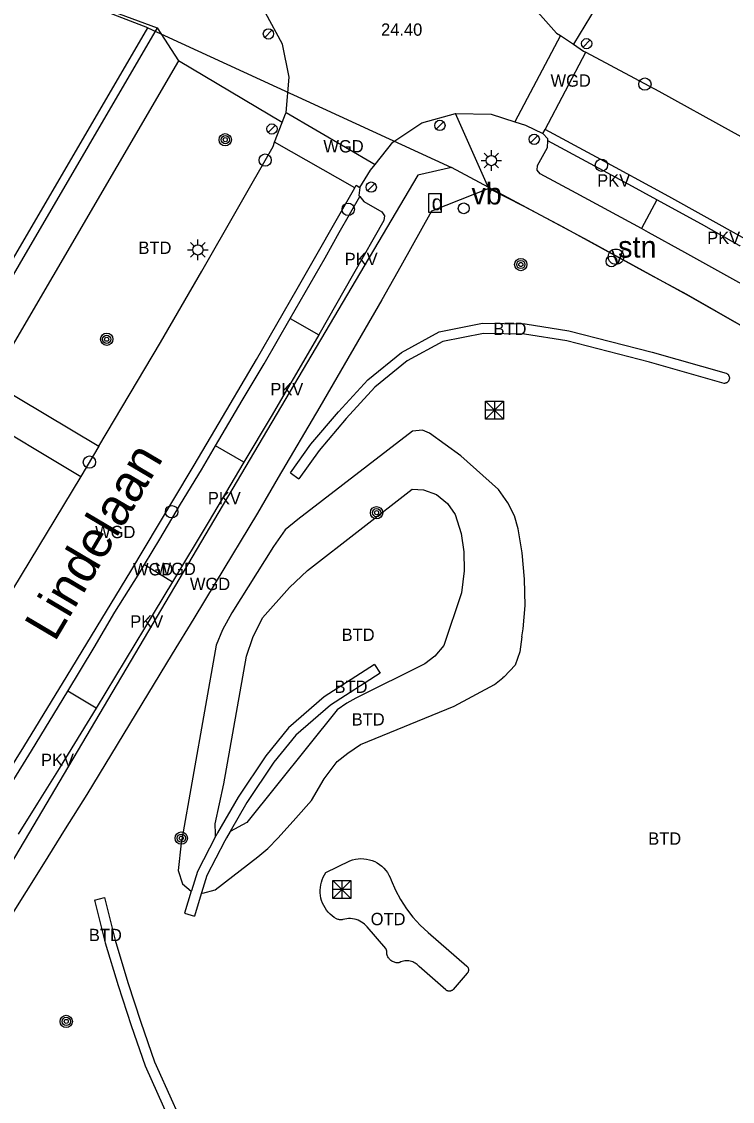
# Model space of a CAD drawing. Extents: x 198240 to 198429, y 356553 to 356721.
# Drawn here: x 198292.1 to 198326.7, y 356629.6 to 356682.2 of the extents above; entities that cross this region are included whole.
import ezdxf

# ---------------------------------------------------------------- set-up
doc = ezdxf.new("R2010")
doc.units = 0
for name, color, linetype in [('Afsluitpaal', 7, 'Continuous'), ('Afvalbak', 7, 'Continuous'), ('begroeid terreindeel kenmerkpunt', 7, 'Continuous'), ('BOOM', 7, 'Continuous'), ('Dispenser', 7, 'Continuous'), ('Grens beheer openbare ruimte wegbeheer', 7, 'Continuous'), ('grens individueel parkeervak', 7, 'Continuous'), ('Grens maaiveld', 7, 'Continuous'), ('Hoogtepunt', 7, 'Continuous'), ('identificerend kenmerkpunt parkeervak', 7, 'Continuous'), ('kant verharding', 7, 'Continuous'), ('kolk', 7, 'Continuous'), ('LICHTMAST', 7, 'Continuous'), ('onbegroeid terreindeel kenmerkpunt', 7, 'Continuous'), ('openbare ruimte label tekst', 7, 'Continuous'), ('perceelsgrens_definitief', 7, 'Continuous'), ('Speelvoorziening', 7, 'Continuous'), ('straatnaambord', 7, 'Continuous'), ('Verkeersbordpaal', 7, 'Continuous'), ('vlakafsluiter', 7, 'Continuous'), ('wegdeel kenmerkpunt', 7, 'Continuous'), ('weginrichtingselement lijn', 7, 'Continuous')]:
    doc.layers.add(name, color=color, linetype=linetype)

msp = doc.modelspace()

# ---------------------------------------------------------------- linework, layer by layer
at = {"layer": 'Afsluitpaal'}
for p, q in [((198304.255, 356681.768), (198303.905, 356681.411)), ((198319.751, 356681.296), (198319.401, 356680.939)), ((198304.428, 356677.142), (198304.078, 356676.785)), ((198312.607, 356677.317), (198312.257, 356676.96)), ((198317.2, 356676.638), (198316.85, 356676.281)), ((198309.263, 356674.313), (198308.913, 356673.956))]:
    msp.add_line(p, q, dxfattribs=at)
for centre in [(198304.082, 356681.588), (198319.578, 356681.116), (198304.255, 356676.962), (198312.434, 356677.137), (198317.027, 356676.458), (198309.09, 356674.133)]:
    msp.add_circle(centre, 0.25, dxfattribs=at)
at = {"layer": 'Afvalbak'}
msp.add_circle((198321.005, 356670.743), 0.375, dxfattribs=at)
msp.add_circle((198321.005, 356670.743), 0.375, dxfattribs=at)
at = {"layer": 'BOOM'}
for centre, radius in [((198301.981, 356676.439), 0.3), ((198301.981, 356676.439), 0.2), ((198301.981, 356676.439), 0.1), ((198316.373, 356670.362), 0.3), ((198316.373, 356670.362), 0.2), ((198316.373, 356670.362), 0.1), ((198296.207, 356666.724), 0.3), ((198296.207, 356666.724), 0.2), ((198296.207, 356666.724), 0.1), ((198309.35, 356658.281), 0.3), ((198309.35, 356658.281), 0.2), ((198309.35, 356658.281), 0.1), ((198299.841, 356642.437), 0.3), ((198299.841, 356642.437), 0.2), ((198299.841, 356642.437), 0.1), ((198294.238, 356633.513), 0.3), ((198294.238, 356633.513), 0.2), ((198294.238, 356633.513), 0.1)]:
    msp.add_circle(centre, radius, dxfattribs=at)
at = {"layer": 'Dispenser'}
msp.add_lwpolyline([(198311.878, 356672.913), (198312.512, 356672.913), (198312.512, 356673.801), (198311.878, 356673.801)], close=True, dxfattribs=at)
at = {"layer": 'Grens beheer openbare ruimte wegbeheer'}
for p, q in [((198318.297, 356681.511), (198316.075, 356677.313)), ((198304.947, 356677.77), (198309.283, 356675.24))]:
    msp.add_line(p, q, dxfattribs=at)
at = {"layer": 'grens individueel parkeervak'}
for p, q in [((198323.004, 356673.505), (198322.242, 356672.111)), ((198305.144, 356667.741), (198306.53, 356666.941)), ((198302.887, 356660.742), (198301.505, 356661.539)), ((198298.049, 356655.752), (198299.406, 356654.919)), ((198295.687, 356648.769), (198294.317, 356649.594))]:
    msp.add_line(p, q, dxfattribs=at)
at = {"layer": 'Grens maaiveld'}
for p, q in [((198317.553, 356676.932), (198319.532, 356680.702)), ((198317.45, 356676.736), (198317.553, 356676.932)), ((198308.283, 356674.098), (198304.386, 356676.319)), ((198310.555, 356666.086), (198312.403, 356667.091)), ((198312.403, 356667.091), (198314.505, 356667.501)), ((198314.505, 356667.501), (198316.591, 356667.47)), ((198316.591, 356667.47), (198318.709, 356667.13)), ((198318.709, 356667.13), (198322.776, 356666.095)), ((198312.575, 356666.615), (198310.835, 356665.67)), ((198314.549, 356667.001), (198312.575, 356666.615)), ((198316.547, 356666.97), (198314.549, 356667.001)), ((198318.607, 356666.64), (198316.547, 356666.97)), ((198322.646, 356665.613), (198318.607, 356666.64)), ((198308.919, 356664.751), (198310.555, 356666.086)), ((198322.776, 356666.095), (198326.379, 356665.067)), ((198310.835, 356665.67), (198309.263, 356664.387)), ((198326.273, 356664.577), (198322.646, 356665.613)), ((198326.379, 356665.067), (198326.398, 356665.057)), ((198326.398, 356665.057), (198326.417, 356665.045)), ((198326.417, 356665.045), (198326.434, 356665.032)), ((198326.434, 356665.032), (198326.45, 356665.018)), ((198326.45, 356665.018), (198326.465, 356665.002)), ((198326.465, 356665.002), (198326.479, 356664.985)), ((198326.479, 356664.985), (198326.491, 356664.967)), ((198326.491, 356664.967), (198326.501, 356664.948)), ((198326.501, 356664.948), (198326.51, 356664.928)), ((198307.5, 356663.191), (198308.919, 356664.751)), ((198326.294, 356664.578), (198326.273, 356664.577)), ((198326.316, 356664.581), (198326.294, 356664.578)), ((198326.337, 356664.585), (198326.316, 356664.581)), ((198326.358, 356664.592), (198326.337, 356664.585)), ((198326.378, 356664.6), (198326.358, 356664.592)), ((198326.397, 356664.61), (198326.378, 356664.6)), ((198326.416, 356664.621), (198326.397, 356664.61)), ((198326.433, 356664.634), (198326.416, 356664.621)), ((198326.45, 356664.648), (198326.433, 356664.634)), ((198326.465, 356664.664), (198326.45, 356664.648)), ((198326.478, 356664.681), (198326.465, 356664.664)), ((198326.49, 356664.699), (198326.478, 356664.681)), ((198326.501, 356664.718), (198326.49, 356664.699)), ((198326.51, 356664.737), (198326.501, 356664.718)), ((198326.51, 356664.928), (198326.518, 356664.908)), ((198326.517, 356664.758), (198326.51, 356664.737)), ((198326.523, 356664.779), (198326.517, 356664.758)), ((198326.518, 356664.908), (198326.523, 356664.887)), ((198326.523, 356664.887), (198326.527, 356664.865)), ((198326.526, 356664.8), (198326.523, 356664.779)), ((198326.528, 356664.822), (198326.526, 356664.8)), ((198326.527, 356664.865), (198326.528, 356664.844)), ((198326.528, 356664.844), (198326.528, 356664.822)), ((198309.263, 356664.387), (198307.874, 356662.861)), ((198306.153, 356661.617), (198307.5, 356663.191)), ((198307.874, 356662.861), (198306.547, 356661.309)), ((198305.155, 356660.219), (198306.153, 356661.617)), ((198306.547, 356661.309), (198305.561, 356659.929)), ((198305.155, 356660.219), (198305.561, 356659.929)), ((198309.252, 356650.89), (198309.522, 356650.47)), ((198300.326, 356639.856), (198299.998, 356638.792)), ((198300.808, 356639.723), (198300.476, 356638.644)), ((198299.998, 356638.792), (198300.476, 356638.644))]:
    msp.add_line(p, q, dxfattribs=at)
for points in [[(198372.981, 356641.75), (198367.706, 356645.661), (198366.187, 356646.802), (198364.538, 356647.958), (198362.833, 356649.176), (198361.195, 356650.33), (198359.548, 356651.463), (198357.799, 356652.691), (198352.878, 356655.977), (198347.848, 356659.26), (198346.187, 356660.353), (198344.459, 356661.463), (198342.759, 356662.483), (198340.988, 356663.592), (198339.269, 356664.603), (198335.834, 356666.664), (198332.346, 356668.725), (198327.175, 356671.678), (198323.573, 356673.677), (198320.05, 356675.592), (198317.553, 356676.932)], [(198286.537, 356637.898), (198290.083, 356643.54), (198292.172, 356646.883), (198294.288, 356650.332), (198295.232, 356651.912), (198297.381, 356655.439), (198299.42, 356658.858), (198300.465, 356660.59), (198301.471, 356662.302), (198303.507, 356665.731), (198304.495, 356667.459), (198305.49, 356669.172), (198308.283, 356674.098)], [(198308.283, 356674.098), (198308.355, 356674.225), (198308.541, 356674.108)], [(198309.252, 356650.89), (198306.8, 356649.312), (198305.062, 356647.807), (198303.951, 356646.439), (198302.602, 356644.434), (198301.602, 356642.698), (198301.516, 356642.533)], [(198309.522, 356650.47), (198307.1, 356648.91), (198305.422, 356647.457), (198304.353, 356646.141), (198303.026, 356644.17), (198302.217, 356642.764)], [(198301.509, 356642.519), (198300.621, 356640.812), (198300.33, 356639.871)], [(198301.96, 356642.303), (198301.085, 356640.622), (198300.821, 356639.766)], [(198308.316, 356641.414), (198308.452, 356641.434), (198308.59, 356641.441), (198308.728, 356641.436), (198308.865, 356641.418), (198309, 356641.388), (198309.132, 356641.346), (198309.259, 356641.293), (198309.381, 356641.228), (198309.497, 356641.153), (198309.606, 356641.067), (198309.706, 356640.972), (198309.797, 356640.869), (198309.879, 356640.758), (198309.951, 356640.639), (198310.012, 356640.515), (198310.061, 356640.386), (198310.267, 356639.904), (198310.513, 356639.442), (198310.798, 356639.001), (198311.119, 356638.587), (198311.474, 356638.201), (198311.86, 356637.846), (198313.744, 356636.204), (198313.759, 356636.19), (198313.772, 356636.174), (198313.785, 356636.157), (198313.796, 356636.14), (198313.805, 356636.121), (198313.813, 356636.101), (198313.819, 356636.081), (198313.823, 356636.061), (198313.825, 356636.04), (198313.825, 356636.019), (198313.824, 356635.999), (198313.821, 356635.978), (198313.816, 356635.958), (198313.81, 356635.938), (198313.801, 356635.919), (198313.791, 356635.901), (198313.78, 356635.883), (198313.767, 356635.867), (198313.071, 356635.069), (198313.056, 356635.053), (198313.04, 356635.039), (198313.023, 356635.027), (198313.005, 356635.016), (198312.986, 356635.006), (198312.966, 356634.998), (198312.945, 356634.992), (198312.924, 356634.988), (198312.903, 356634.986), (198312.882, 356634.985), (198312.861, 356634.986), (198312.84, 356634.99), (198312.819, 356634.995), (198312.799, 356635.001), (198312.779, 356635.01), (198312.76, 356635.02), (198312.742, 356635.032), (198312.726, 356635.045), (198311.422, 356636.182), (198311.379, 356636.231), (198311.333, 356636.277), (198311.282, 356636.318), (198311.228, 356636.355), (198311.171, 356636.387), (198311.111, 356636.414), (198311.05, 356636.436), (198310.987, 356636.453), (198310.922, 356636.465), (198310.857, 356636.47), (198310.792, 356636.471), (198310.726, 356636.465), (198310.662, 356636.454), (198310.599, 356636.438), (198310.537, 356636.416), (198310.477, 356636.39), (198310.457, 356636.381), (198310.437, 356636.374), (198310.415, 356636.368), (198310.394, 356636.365), (198310.372, 356636.364), (198310.35, 356636.364), (198310.304, 356636.369), (198310.259, 356636.378), (198310.214, 356636.391), (198310.171, 356636.408), (198310.129, 356636.428), (198310.089, 356636.452), (198310.051, 356636.479), (198310.016, 356636.509), (198309.983, 356636.542), (198309.954, 356636.578), (198309.927, 356636.616), (198309.904, 356636.656), (198309.884, 356636.698), (198309.868, 356636.742), (198309.856, 356636.787), (198309.847, 356636.832), (198309.842, 356636.879), (198309.842, 356636.925), (198309.841, 356636.944), (198309.839, 356636.963), (198309.835, 356636.982), (198309.83, 356637.001), (198309.823, 356637.018), (198309.814, 356637.035), (198309.803, 356637.052), (198309.792, 356637.067), (198308.897, 356638.111), (198308.833, 356638.18), (198308.765, 356638.244), (198308.691, 356638.302), (198308.613, 356638.354), (198308.531, 356638.399), (198308.445, 356638.438), (198308.357, 356638.469), (198308.266, 356638.493), (198308.174, 356638.509), (198308.08, 356638.518), (198307.986, 356638.519), (198307.893, 356638.512), (198307.8, 356638.498), (198307.709, 356638.476), (198307.67, 356638.467), (198307.63, 356638.462), (198307.59, 356638.461), (198307.55, 356638.463), (198307.51, 356638.47), (198307.471, 356638.48), (198307.434, 356638.494), (198307.398, 356638.512), (198307.287, 356638.58), (198307.182, 356638.657), (198307.084, 356638.742), (198306.994, 356638.835), (198306.912, 356638.936), (198306.838, 356639.043), (198306.774, 356639.155), (198306.719, 356639.273), (198306.675, 356639.395), (198306.641, 356639.52), (198306.617, 356639.648), (198306.604, 356639.777), (198306.603, 356639.907), (198306.612, 356640.036), (198306.632, 356640.165), (198306.662, 356640.291), (198306.703, 356640.414), (198306.754, 356640.533), (198306.815, 356640.648), (198306.886, 356640.757), (198308.05, 356641.339), (198308.181, 356641.382), (198308.316, 356641.414)]]:
    msp.add_lwpolyline(points, dxfattribs=at)
at = {"layer": 'kant verharding'}
for p, q in [((198324.168, 356689.714), (198318.94, 356681.083)), ((198318.297, 356681.511), (198318.94, 356681.083)), ((198304.756, 356677.274), (198299.71, 356680.28)), ((198304.756, 356677.274), (198304.922, 356677.704)), ((198304.922, 356677.704), (198304.947, 356677.77)), ((198304.386, 356676.319), (198304.756, 356677.274)), ((198295.83, 356661.522), (198294.945, 356660.041)), ((198301.516, 356642.533), (198301.509, 356642.519)), ((198300.33, 356639.871), (198300.326, 356639.856)), ((198300.821, 356639.766), (198300.808, 356639.723)), ((198295.609, 356639.419), (198296.093, 356639.541))]:
    msp.add_line(p, q, dxfattribs=at)
for points in [[(198239.787, 356698.674), (198277.877, 356688.756), (198279.573, 356688.328), (198281.722, 356687.74), (198283.655, 356687.172), (198285.635, 356686.576), (198287.401, 356686.002), (198289.29, 356685.363), (198291.23, 356684.694), (198293.016, 356684.031), (198294.971, 356683.265), (198298.672, 356681.879)], [(198317.228, 356690.174), (198316.569, 356688.783), (198316.101, 356687.293), (198316.037, 356685.727), (198316.368, 356684.197), (198317.077, 356682.795), (198318.116, 356681.632), (198318.297, 356681.511)], [(198304.947, 356677.77), (198305.092, 356679.489), (198304.764, 356681.085), (198303.938, 356682.621), (198302.718, 356683.87), (198301.331, 356684.631), (198300.854, 356684.816)], [(198298.672, 356681.879), (198281.729, 356652.893), (198280.805, 356651.439), (198272.725, 356638.444), (198270.553, 356635.006), (198264.327, 356625.306), (198262.967, 356623.203)], [(198318.94, 356681.083), (198319.431, 356680.756), (198319.532, 356680.702)], [(198299.71, 356680.28), (198290.566, 356664.656), (198295.83, 356661.522)], [(198319.532, 356680.702), (198323.087, 356678.797), (198326.611, 356676.862), (198328.348, 356675.892), (198331.824, 356673.931), (198333.616, 356672.898)], [(198309.283, 356675.24), (198310.144, 356676.323), (198311.551, 356677.266), (198313.199, 356677.719)], [(198313.199, 356677.719), (198314.929, 356677.677), (198316.075, 356677.313)], [(198316.075, 356677.313), (198316.599, 356677.146), (198317.45, 356676.736)], [(198317.684, 356676.383), (198317.69, 356676.483), (198317.45, 356676.736)], [(198295.83, 356661.522), (198298.827, 356666.573), (198300.844, 356670.034), (198304.306, 356676.111), (198304.386, 356676.319)], [(198322.242, 356672.111), (198319.074, 356673.829), (198317.31, 356674.771), (198317.161, 356674.963), (198317.181, 356675.183), (198317.664, 356676.064), (198317.684, 356676.383)], [(198323.004, 356673.505), (198321.63, 356674.257), (198317.684, 356676.383)], [(198308.541, 356674.108), (198309.058, 356674.957), (198309.283, 356675.24)], [(198314.814, 356674.063), (198312.029, 356672.963), (198310.527, 356670.277), (198309.599, 356668.644), (198306.585, 356663.435), (198304.556, 356659.989), (198303.55, 356658.264), (198301.482, 356654.843), (198300.453, 356653.124), (198299.402, 356651.409), (198295.243, 356644.568), (198294.178, 356642.884), (198293.122, 356641.182), (198288.971, 356634.577)], [(198308.541, 356674.108), (198308.488, 356673.718), (198308.529, 356673.667)], [(198352.51, 356651.714), (198350.276, 356653.164), (198348.4, 356654.399), (198343.742, 356657.419), (198341.543, 356658.825), (198339.43, 356660.09), (198337.442, 356661.338), (198333.99, 356663.38), (198332.34, 356664.377), (198330.533, 356665.43), (198328.787, 356666.422), (198324.464, 356668.899), (198322.677, 356669.861), (198318.431, 356672.186), (198316.529, 356673.188), (198314.814, 356674.063)], [(198305.144, 356667.741), (198306.85, 356670.689), (198307.533, 356671.918), (198308.529, 356673.667)], [(198308.529, 356673.667), (198308.721, 356673.427), (198309.597, 356672.934), (198309.739, 356672.74), (198309.699, 356672.508), (198308.226, 356669.905), (198306.53, 356666.941)], [(198328.199, 356670.612), (198325.17, 356672.32), (198323.004, 356673.505)], [(198327.419, 356669.24), (198324.358, 356670.953), (198322.598, 356671.918), (198322.242, 356672.111)], [(198301.505, 356661.539), (198302.802, 356663.746), (198303.88, 356665.536), (198305.144, 356667.741)], [(198306.53, 356666.941), (198306.24, 356666.433), (198304.217, 356662.969), (198302.887, 356660.742)], [(198284.31, 356653.964), (198289.691, 356663.193), (198294.945, 356660.041)], [(198316.429, 356652.235), (198316.484, 356652.634), (198316.587, 356653.755), (198316.545, 356655.042), (198316.432, 356656.331), (198316.25, 356657.493), (198316.059, 356658.12), (198315.746, 356658.761), (198315.289, 356659.414), (198313.447, 356661.057), (198311.934, 356662.151), (198311.591, 356662.306), (198311.105, 356662.242), (198305.509, 356657.956), (198304.902, 356657.439), (198304.328, 356656.64), (198302.293, 356653.401), (198301.842, 356652.58), (198301.543, 356651.839), (198299.839, 356642.193), (198299.689, 356640.868), (198299.905, 356640.205), (198300.326, 356639.856)], [(198298.049, 356655.752), (198298.798, 356656.987), (198299.804, 356658.69), (198300.826, 356660.375), (198301.505, 356661.539)], [(198302.887, 356660.742), (198301.151, 356657.811), (198299.406, 356654.919)], [(198294.945, 356660.041), (198291.623, 356654.549), (198290.581, 356652.845), (198289.527, 356651.142)], [(198301.509, 356642.519), (198301.499, 356642.653), (198301.486, 356643.136), (198301.904, 356645.088), (198303.008, 356651.291), (198303.328, 356652.204), (198303.798, 356653.155), (198305.104, 356654.635), (198305.98, 356655.468), (198311.087, 356659.428), (198311.634, 356659.392), (198312.267, 356659.162), (198312.803, 356658.731), (198313.175, 356658.191), (198313.468, 356657.265), (198313.6, 356656.369), (198313.61, 356655.443), (198313.478, 356654.379), (198312.628, 356651.822), (198312.184, 356651.3), (198311.698, 356650.93), (198308.346, 356649.254), (198307.895, 356649.01), (198307.426, 356648.683), (198303.03, 356643.205), (198302.217, 356642.764)], [(198294.317, 356649.594), (198295.594, 356651.712), (198296.608, 356653.444), (198297.739, 356655.236), (198298.049, 356655.752)], [(198299.406, 356654.919), (198298.054, 356652.665), (198295.687, 356648.769)], [(198316.429, 356652.235), (198316.327, 356651.5), (198316.096, 356650.851), (198315.561, 356650.286), (198315.5, 356650.239)], [(198300.821, 356639.766), (198300.889, 356639.758), (198301.484, 356639.927), (198303.572, 356641.529), (198304.059, 356641.936), (198304.551, 356642.45), (198305.422, 356643.411), (198306.175, 356644.274), (198306.8, 356645.32), (198307.426, 356646.163), (198307.946, 356646.569), (198308.572, 356646.993), (198313.128, 356648.861), (198315.084, 356649.919), (198315.5, 356650.239)], [(198290.544, 356643.476), (198292.54, 356646.68), (198294.317, 356649.594)], [(198295.687, 356648.769), (198293.888, 356645.827), (198292.831, 356644.137), (198291.898, 356642.624)], [(198302.217, 356642.764), (198302.04, 356642.458), (198301.96, 356642.303)], [(198295.609, 356639.419), (198296.132, 356637.335), (198296.768, 356635.258), (198297.401, 356633.318), (198298.077, 356631.357), (198298.966, 356629.358), (198299.856, 356627.399), (198300.835, 356625.473), (198301.904, 356623.589), (198303.061, 356621.754), (198304.4, 356620.082), (198306.161, 356618.711), (198308.223, 356617.871), (198310.375, 356617.558), (198311.788, 356617.522), (198313.219, 356617.658)], [(198296.093, 356639.541), (198296.614, 356637.469), (198297.244, 356635.408), (198297.875, 356633.478), (198298.543, 356631.541), (198299.422, 356629.562), (198300.306, 356627.615), (198301.275, 356625.709), (198302.334, 356623.845), (198303.469, 356622.044), (198304.754, 356620.44), (198306.413, 356619.147), (198308.355, 356618.357), (198310.417, 356618.058), (198311.77, 356618.022), (198313.171, 356618.156)]]:
    msp.add_lwpolyline(points, dxfattribs=at)
at = {"layer": 'kolk'}
for centre in [(198322.416, 356679.144), (198303.924, 356675.446), (198320.299, 356675.195), (198307.966, 356673.05), (198295.365, 356660.745), (198299.371, 356658.33)]:
    msp.add_circle(centre, 0.3, dxfattribs=at)
at = {"layer": 'LICHTMAST'}
for p, q in [((198314.76, 356675.601), (198314.583, 356675.778)), ((198314.937, 356675.674), (198314.937, 356675.924)), ((198315.114, 356675.601), (198315.291, 356675.778)), ((198314.437, 356675.424), (198314.687, 356675.424)), ((198314.583, 356675.07), (198314.76, 356675.247)), ((198314.937, 356674.924), (198314.937, 356675.174)), ((198315.291, 356675.07), (198315.114, 356675.247)), ((198315.187, 356675.424), (198315.437, 356675.424)), ((198300.473, 356671.251), (198300.296, 356671.428)), ((198300.65, 356671.324), (198300.65, 356671.574)), ((198300.827, 356671.251), (198301.004, 356671.428)), ((198300.15, 356671.074), (198300.4, 356671.074)), ((198300.296, 356670.72), (198300.473, 356670.897)), ((198300.65, 356670.574), (198300.65, 356670.824)), ((198301.004, 356670.72), (198300.827, 356670.897)), ((198300.9, 356671.074), (198301.15, 356671.074))]:
    msp.add_line(p, q, dxfattribs=at)
for centre in [(198314.937, 356675.424), (198300.65, 356671.074)]:
    msp.add_circle(centre, 0.25, dxfattribs=at)
at = {"layer": 'perceelsgrens_definitief'}
for points in [[(198298.205, 356681.89), (198294.757, 356683.22), (198291.286, 356684.488), (198287.793, 356685.695), (198284.279, 356686.84), (198280.746, 356687.922), (198277.194, 356688.941), (198273.624, 356689.897), (198270.038, 356690.79)], [(198243.211, 356592.912), (198264.167, 356625.417), (198275.594, 356643.523), (198286.547, 356661.91), (198298.205, 356681.89)], [(198298.205, 356681.89), (198312.991, 356675.082)], [(198312.991, 356675.082), (198311.361, 356674.706), (198287.433, 356634.266)], [(198314.815, 356674.112), (198312.991, 356675.082)], [(198370.586, 356638.823), (198366.164, 356642.103), (198361.698, 356645.323), (198357.189, 356648.483), (198352.638, 356651.581), (198348.046, 356654.619), (198343.413, 356657.594), (198338.741, 356660.506), (198334.03, 356663.356), (198329.281, 356666.142), (198324.495, 356668.863), (198319.673, 356671.52), (198314.815, 356674.112)]]:
    msp.add_lwpolyline(points, dxfattribs=at)
at = {"layer": 'Speelvoorziening'}
for p, q in [((198314.655, 356663.707), (198315.535, 356663.707)), ((198314.655, 356662.827), (198314.655, 356663.707)), ((198314.655, 356663.707), (198315.535, 356662.827)), ((198314.655, 356662.827), (198315.535, 356663.707)), ((198315.095, 356663.707), (198315.095, 356662.827)), ((198315.535, 356663.707), (198315.535, 356662.827)), ((198315.535, 356663.267), (198314.655, 356663.267)), ((198315.535, 356662.827), (198314.655, 356662.827)), ((198307.211, 356640.372), (198308.091, 356640.372)), ((198307.211, 356639.492), (198307.211, 356640.372)), ((198307.211, 356640.372), (198308.091, 356639.492)), ((198307.211, 356639.492), (198308.091, 356640.372)), ((198307.651, 356640.372), (198307.651, 356639.492)), ((198308.091, 356640.372), (198308.091, 356639.492)), ((198308.091, 356639.932), (198307.211, 356639.932)), ((198308.091, 356639.492), (198307.211, 356639.492))]:
    msp.add_line(p, q, dxfattribs=at)
at = {"layer": 'straatnaambord'}
msp.add_circle((198320.786, 356670.514), 0.263, dxfattribs=at)
msp.add_circle((198320.786, 356670.514), 0.263, dxfattribs=at)
at = {"layer": 'Verkeersbordpaal'}
msp.add_circle((198313.593, 356673.098), 0.263, dxfattribs=at)
at = {"layer": 'vlakafsluiter'}
for p, q in [((198298.672, 356681.879), (198299.71, 356680.28)), ((198314.814, 356674.063), (198313.199, 356677.719))]:
    msp.add_line(p, q, dxfattribs=at)
at = {"layer": 'weginrichtingselement lijn'}
msp.add_line((198317.45, 356676.736), (198317.553, 356676.932), dxfattribs=at)
for points in [[(198372.981, 356641.75), (198367.706, 356645.661), (198366.187, 356646.802), (198364.538, 356647.958), (198362.833, 356649.176), (198361.195, 356650.33), (198359.548, 356651.463), (198357.799, 356652.691), (198352.878, 356655.977), (198347.848, 356659.26), (198346.187, 356660.353), (198344.459, 356661.463), (198342.759, 356662.483), (198340.988, 356663.592), (198339.269, 356664.603), (198335.834, 356666.664), (198332.346, 356668.725), (198327.175, 356671.678), (198323.573, 356673.677), (198320.05, 356675.592), (198317.553, 356676.932)], [(198286.537, 356637.898), (198290.083, 356643.54), (198292.172, 356646.883), (198294.288, 356650.332), (198295.232, 356651.912), (198297.381, 356655.439), (198299.42, 356658.858), (198300.465, 356660.59), (198301.471, 356662.302), (198303.507, 356665.731), (198304.495, 356667.459), (198305.49, 356669.172), (198308.283, 356674.098)], [(198308.283, 356674.098), (198308.355, 356674.225), (198308.541, 356674.108)]]:
    msp.add_lwpolyline(points, dxfattribs=at)

# ---------------------------------------------------------------- texts
at = {"layer": 'Afvalbak'}
msp.add_text('V', height=0.686, dxfattribs=at).set_placement((198320.777, 356670.372))
msp.add_text('V', height=0.686, dxfattribs=at).set_placement((198320.777, 356670.372))
at = {"layer": 'begroeid terreindeel kenmerkpunt'}
for p in [(198297.755, 356670.878), (198315.041, 356666.931), (198307.648, 356652.041), (198307.302, 356649.509), (198308.138, 356647.92), (198322.577, 356642.116), (198295.341, 356637.422)]:
    msp.add_text('BTD', height=0.6, dxfattribs=at).set_placement(p)
at = {"layer": 'Dispenser'}
msp.add_text('d', height=0.753, dxfattribs=at).set_placement((198312.031, 356673.004))
at = {"layer": 'Hoogtepunt'}
msp.add_text('24.40', height=0.6, dxfattribs=at).set_placement((198309.567, 356681.501))
msp.add_text('24.40', height=0.6, dxfattribs=at).set_placement((198309.567, 356681.501))
at = {"layer": 'identificerend kenmerkpunt parkeervak'}
for p in [(198320.091, 356674.159), (198325.447, 356671.362), (198307.796, 356670.333), (198304.174, 356663.998), (198301.132, 356658.693), (198297.355, 356652.684), (198293.008, 356645.945)]:
    msp.add_text('PKV', height=0.6, dxfattribs=at).set_placement(p)
at = {"layer": 'onbegroeid terreindeel kenmerkpunt'}
msp.add_text('OTD', height=0.6, dxfattribs=at).set_placement((198309.063, 356638.199))
at = {"layer": 'openbare ruimte label tekst'}
msp.add_text('Lindelaan', height=1.8, rotation=59.4, dxfattribs=at).set_placement((198293.677, 356651.948))
at = {"layer": 'straatnaambord'}
msp.add_text('stn', height=1.05, dxfattribs=at).set_placement((198321.11, 356670.699))
at = {"layer": 'Verkeersbordpaal'}
msp.add_text('vb', height=1.05, dxfattribs=at).set_placement((198313.969, 356673.288))
at = {"layer": 'wegdeel kenmerkpunt'}
for p in [(198317.82, 356679.02), (198306.76, 356675.819), (198295.642, 356657.041), (198297.488, 356655.228), (198298.588, 356655.246), (198300.259, 356654.512)]:
    msp.add_text('WGD', height=0.6, dxfattribs=at).set_placement(p)

doc.saveas('drawing.dxf')
